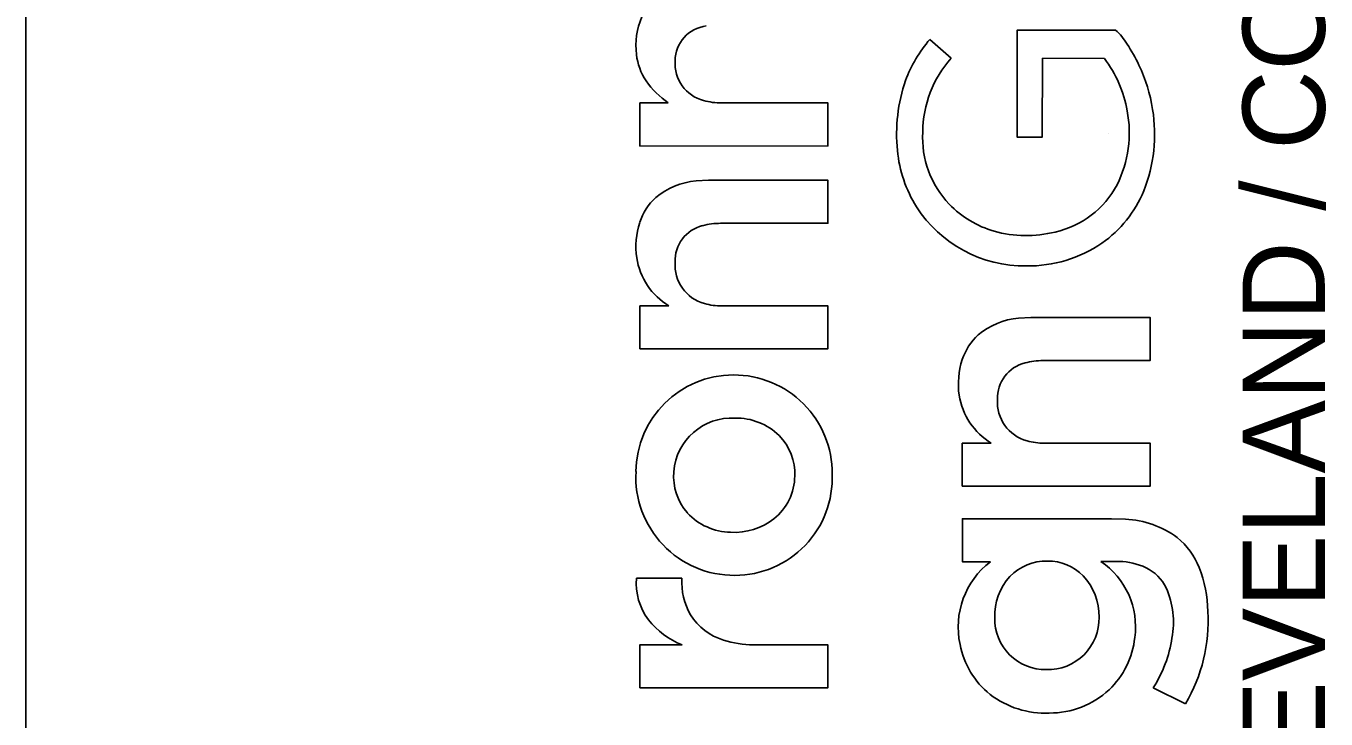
# Model space of a CAD drawing. Extents: x 0 to 1700, y 0 to 1100.
# Drawn here: x 1600 to 1645.05, y 154.72 to 178.74 of the extents above; entities that cross this region are included whole.
import ezdxf

# ---------------------------------------------------------------- set-up
doc = ezdxf.new("R2010")
doc.units = 0
doc.layers.add('SH_Border', color=7, linetype='Continuous')
doc.layers.add('SH_Data', color=7, linetype='Continuous')

msp = doc.modelspace()

# ---------------------------------------------------------------- linework, layer by layer
at = {"layer": 'SH_Border'}
msp.add_line((1600, 25), (1600, 1075), dxfattribs=at)
at = {"layer": 'SH_Data'}
for p, q in [((1634.34, 178.592), (1637.758, 178.596)), ((1634.34, 174.889), (1634.34, 178.592)), ((1631.318, 178.274), (1632.057, 177.621)), ((1635.224, 177.62), (1635.216, 174.888)), ((1637.368, 177.614), (1635.224, 177.62)), ((1621.271, 174.576), (1621.272, 176.069)), ((1621.272, 176.069), (1622.257, 176.069)), ((1624.103, 176.069), (1627.786, 176.068)), ((1627.786, 176.068), (1627.786, 174.578)), ((1635.216, 174.888), (1634.34, 174.889)), ((1637.5, 175), (1637.5, 175)), ((1627.786, 174.578), (1621.271, 174.576)), ((1623.219, 173.368), (1623.645, 173.391)), ((1623.645, 173.391), (1627.785, 173.391)), ((1627.785, 173.391), (1627.786, 171.902)), ((1627.786, 171.902), (1624.07, 171.898)), ((1621.271, 169.033), (1622.276, 169.036)), ((1621.271, 167.543), (1621.271, 169.033)), ((1624.111, 169.036), (1627.785, 169.036)), ((1627.785, 169.036), (1627.786, 167.548)), ((1634.392, 168.61), (1634.817, 168.633)), ((1634.817, 168.633), (1638.958, 168.633)), ((1638.958, 168.633), (1638.958, 167.144)), ((1627.786, 167.548), (1621.271, 167.543)), ((1638.958, 167.144), (1635.242, 167.14)), ((1632.444, 164.275), (1633.449, 164.277)), ((1632.444, 162.785), (1632.444, 164.275)), ((1635.284, 164.277), (1638.957, 164.277)), ((1638.957, 164.277), (1638.958, 162.789)), ((1638.958, 162.789), (1632.444, 162.785)), ((1632.445, 160.168), (1632.445, 161.661)), ((1632.445, 161.661), (1637.618, 161.661)), ((1637.618, 161.661), (1638.096, 161.643)), ((1633.418, 160.168), (1632.445, 160.168)), ((1637.881, 160.178), (1637.243, 160.181)), ((1621.149, 159.597), (1622.727, 159.597)), ((1621.271, 155.797), (1621.271, 157.289)), ((1621.271, 157.289), (1622.736, 157.289)), ((1625.206, 157.29), (1627.786, 157.287)), ((1627.786, 157.287), (1627.782, 155.797)), ((1627.782, 155.797), (1621.271, 155.797)), ((1640.18, 155.245), (1639.06, 155.799))]:
    msp.add_line(p, q, dxfattribs=at)
for points in [[(1637.368, 177.614), (1635.224, 177.62), (1635.216, 174.888), (1634.34, 174.889), (1634.34, 178.592), (1637.758, 178.596)], [(1631.318, 178.274), (1632.057, 177.621)], [(1621.271, 174.576), (1621.272, 176.069), (1622.257, 176.069)], [(1624.103, 176.069), (1627.786, 176.068), (1627.786, 174.578), (1621.271, 174.576)], [(1623.219, 173.368), (1623.645, 173.391), (1627.785, 173.391), (1627.786, 171.902), (1624.07, 171.898)], [(1621.271, 167.543), (1621.271, 169.033), (1622.276, 169.036)], [(1624.111, 169.036), (1627.785, 169.036), (1627.786, 167.548), (1621.271, 167.543)], [(1634.392, 168.61), (1634.817, 168.633), (1638.958, 168.633), (1638.958, 167.144), (1635.242, 167.14)], [(1632.444, 162.785), (1632.444, 164.275), (1633.449, 164.277)], [(1635.284, 164.277), (1638.957, 164.277), (1638.958, 162.789), (1632.444, 162.785)], [(1633.418, 160.168), (1632.445, 160.168), (1632.445, 161.661), (1637.618, 161.661), (1638.096, 161.643)], [(1637.881, 160.178), (1637.243, 160.181)], [(1621.149, 159.597), (1622.727, 159.597)], [(1625.206, 157.29), (1627.786, 157.287), (1627.782, 155.797), (1621.271, 155.797)], [(1621.271, 155.797), (1621.271, 157.289), (1622.736, 157.289)], [(1640.18, 155.245), (1639.06, 155.799)]]:
    msp.add_lwpolyline(points, dxfattribs=at)
for centre, radius, start, end in [((1623.572, 178.06), 2.439, 156.0638, 187.3493), ((1623.572, 178.06), 2.439, 156.0638, 187.3493), ((1623.711, 177.528), 1.217, 96.5532, 179.949), ((1623.711, 177.528), 1.217, 96.5532, 179.949), ((1636.249, 176.969), 2.219, 30.9891, 47.161), ((1636.249, 176.969), 2.219, 30.9891, 47.161), ((1635.081, 175.093), 4.928, 139.7948, 159.137), ((1635.081, 175.093), 4.928, 139.7948, 159.137), ((1633.546, 175.009), 5.553, 25.3031, 33.9618), ((1633.546, 175.009), 5.553, 25.3031, 33.9618), ((1623.23, 177.987), 2.091, 186.5579, 213.3885), ((1623.23, 177.987), 2.091, 186.5579, 213.3885), ((1623.804, 177.431), 1.314, 175.722, 255.7863), ((1623.804, 177.431), 1.314, 175.722, 255.7863), ((1634.95, 175.04), 3.877, 138.258, 179.7006), ((1634.95, 175.04), 3.877, 138.258, 179.7006), ((1633.944, 175.049), 4.278, 10.0751, 36.8319), ((1633.944, 175.049), 4.278, 10.0751, 36.8319), ((1633.52, 174.993), 5.583, 8.8034, 25.3348), ((1633.52, 174.993), 5.583, 8.8034, 25.3348), ((1623.943, 178.539), 2.99, 214.7043, 235.6872), ((1623.943, 178.539), 2.99, 214.7043, 235.6872), ((1635.935, 174.984), 5.768, 161.1438, 185.6281), ((1635.935, 174.984), 5.768, 161.1438, 185.6281), ((1624.097, 178.259), 2.19, 253.6672, 270.1498), ((1624.097, 178.259), 2.19, 253.6672, 270.1498), ((1634.212, 175.028), 4.018, 333.4669, 11.0367), ((1634.212, 175.028), 4.018, 333.4669, 11.0367), ((1633.782, 174.989), 5.325, 338.2887, 9.2855), ((1633.782, 174.989), 5.325, 338.2887, 9.2855), ((1634.406, 174.866), 3.338, 176.6658, 223.6912), ((1634.406, 174.866), 3.338, 176.6658, 223.6912), ((1634.668, 174.85), 4.493, 185.5077, 212.0129), ((1634.668, 174.85), 4.493, 185.5077, 212.0129), ((1623.435, 170.884), 2.494, 94.9706, 130.2248), ((1623.435, 170.884), 2.494, 94.9706, 130.2248), ((1634.934, 174.773), 3.26, 282.8815, 331.8147), ((1634.934, 174.773), 3.26, 282.8815, 331.8147), ((1634.918, 174.584), 4.12, 305.0306, 337.6757), ((1634.918, 174.584), 4.12, 305.0306, 337.6757), ((1623.174, 171.301), 2.008, 132.2238, 161.6823), ((1623.174, 171.301), 2.008, 132.2238, 161.6823), ((1634.523, 175.006), 3.519, 224.0215, 253.88), ((1634.523, 175.006), 3.519, 224.0215, 253.88), ((1634.606, 174.874), 4.454, 212.7022, 270.714), ((1634.606, 174.874), 4.454, 212.7022, 270.714), ((1623.936, 171.079), 2.801, 162.274, 187.7917), ((1623.936, 171.079), 2.801, 162.274, 187.7917), ((1623.741, 170.603), 1.249, 103.6868, 182.214), ((1623.741, 170.603), 1.249, 103.6868, 182.214), ((1624.054, 169.598), 2.3, 89.6051, 105.3303), ((1624.054, 169.598), 2.3, 89.6051, 105.3303), ((1634.659, 175.627), 4.154, 254.4535, 283.9512), ((1634.659, 175.627), 4.154, 254.4535, 283.9512), ((1634.715, 174.989), 4.569, 269.3273, 304.1963), ((1634.715, 174.989), 4.569, 269.3273, 304.1963), ((1623.513, 171.071), 2.381, 188.9646, 238.6987), ((1623.513, 171.071), 2.381, 188.9646, 238.6987), ((1623.868, 170.449), 1.378, 175.5844, 255.1382), ((1623.868, 170.449), 1.378, 175.5844, 255.1382), ((1624.092, 171.143), 2.107, 254.0891, 270.5284), ((1624.092, 171.143), 2.107, 254.0891, 270.5284), ((1634.608, 166.125), 2.494, 94.9706, 130.2248), ((1634.608, 166.125), 2.494, 94.9706, 130.2248), ((1634.347, 166.543), 2.008, 132.2238, 161.6823), ((1634.347, 166.543), 2.008, 132.2238, 161.6823), ((1635.109, 166.321), 2.801, 162.274, 187.7917), ((1635.109, 166.321), 2.801, 162.274, 187.7917), ((1635.227, 164.84), 2.3, 89.6051, 105.3303), ((1635.227, 164.84), 2.3, 89.6051, 105.3303), ((1634.914, 165.845), 1.249, 103.6868, 182.214), ((1634.914, 165.845), 1.249, 103.6868, 182.214), ((1624.507, 163.271), 3.37, 89.8476, 179.6405), ((1624.507, 163.271), 3.37, 89.8476, 179.6405), ((1624.529, 163.237), 3.405, 359.5401, 90.2114), ((1624.529, 163.237), 3.405, 359.5401, 90.2114), ((1634.686, 166.312), 2.381, 188.9646, 238.6987), ((1634.686, 166.312), 2.381, 188.9646, 238.6987), ((1635.04, 165.69), 1.378, 175.5844, 255.1382), ((1635.04, 165.69), 1.378, 175.5844, 255.1382), ((1624.461, 163.132), 2.02, 87.0481, 175.5726), ((1624.461, 163.132), 2.02, 87.0481, 175.5726), ((1624.602, 163), 2.149, 45.8426, 90.9801), ((1624.602, 163), 2.149, 45.8426, 90.9801), ((1624.729, 163.211), 1.911, 357.8857, 44.159), ((1624.729, 163.211), 1.911, 357.8857, 44.159), ((1635.264, 166.385), 2.107, 254.0891, 270.5284), ((1635.264, 166.385), 2.107, 254.0891, 270.5284), ((1624.541, 163.104), 3.409, 176.8344, 270.4038), ((1624.541, 163.104), 3.409, 176.8344, 270.4038), ((1624.365, 163.125), 1.924, 175.1538, 221.1471), ((1624.365, 163.125), 1.924, 175.1538, 221.1471), ((1624.562, 163.069), 3.374, 270.0624, 2.3776), ((1624.562, 163.069), 3.374, 270.0624, 2.3776), ((1624.723, 163.159), 1.915, 308.2894, 359.4347), ((1624.723, 163.159), 1.915, 308.2894, 359.4347), ((1624.459, 163.303), 2.114, 223.0999, 268.8089), ((1624.459, 163.303), 2.114, 223.0999, 268.8089), ((1624.548, 163.395), 2.209, 266.5651, 308.0608), ((1624.548, 163.395), 2.209, 266.5651, 308.0608), ((1637.953, 158.394), 3.251, 53.4034, 87.4906), ((1637.953, 158.394), 3.251, 53.4034, 87.4906), ((1638.259, 159.02), 2.571, 21.6075, 50.5577), ((1638.259, 159.02), 2.571, 21.6075, 50.5577), ((1635.146, 157.906), 2.846, 127.3748, 192.2247), ((1635.146, 157.906), 2.846, 127.3748, 192.2247), ((1635.347, 158.464), 1.73, 88.473, 136.4256), ((1635.347, 158.464), 1.73, 88.473, 136.4256), ((1635.407, 158.481), 1.712, 44.2719, 90.4762), ((1635.407, 158.481), 1.712, 44.2719, 90.4762), ((1635.71, 157.914), 2.736, 352.1125, 55.923), ((1635.71, 157.914), 2.736, 352.1125, 55.923), ((1637.833, 157.862), 2.316, 65.0169, 88.8011), ((1637.833, 157.862), 2.316, 65.0169, 88.8011), ((1638.13, 158.578), 1.543, 26.2681, 63.803), ((1638.13, 158.578), 1.543, 26.2681, 63.803), ((1636.535, 158.357), 4.418, 1.1514, 21.3627), ((1636.535, 158.357), 4.418, 1.1514, 21.3627), ((1623.308, 159.441), 2.164, 175.8731, 216.3475), ((1623.308, 159.441), 2.164, 175.8731, 216.3475), ((1625.043, 159.474), 2.32, 176.9688, 209.6064), ((1625.043, 159.474), 2.32, 176.9688, 209.6064), ((1635.571, 158.301), 2.005, 137.4674, 182.3324), ((1635.571, 158.301), 2.005, 137.4674, 182.3324), ((1635.184, 158.3), 1.998, 358.5714, 43.5376), ((1635.184, 158.3), 1.998, 358.5714, 43.5376), ((1636.783, 158.077), 2.976, 349.3073, 23.4307), ((1636.783, 158.077), 2.976, 349.3073, 23.4307), ((1623.733, 159.858), 2.755, 218.0981, 248.7907), ((1623.733, 159.858), 2.755, 218.0981, 248.7907), ((1624.757, 159.407), 2.039, 211.9447, 253.2028), ((1624.757, 159.407), 2.039, 211.9447, 253.2028), ((1635.323, 158.185), 1.755, 178.8821, 271.0837), ((1635.323, 158.185), 1.755, 178.8821, 271.0837), ((1635.409, 158.202), 1.773, 268.2788, 1.5502), ((1635.409, 158.202), 1.773, 268.2788, 1.5502), ((1635.269, 158.122), 5.692, 329.6388, 3.26), ((1635.269, 158.122), 5.692, 329.6388, 3.26), ((1625.233, 160.825), 3.535, 252.4655, 269.573), ((1625.233, 160.825), 3.535, 252.4655, 269.573), ((1635.232, 157.848), 2.919, 190.7518, 231.2892), ((1635.232, 157.848), 2.919, 190.7518, 231.2892), ((1635.494, 157.854), 2.944, 313.742, 353.8554), ((1635.494, 157.854), 2.944, 313.742, 353.8554), ((1635.369, 158.167), 4.385, 327.3149, 351.5748), ((1635.369, 158.167), 4.385, 327.3149, 351.5748), ((1635.316, 158.056), 3.134, 232.4606, 272.5902), ((1635.316, 158.056), 3.134, 232.4606, 272.5902), ((1635.477, 157.951), 3.026, 269.6361, 312.7088), ((1635.477, 157.951), 3.026, 269.6361, 312.7088)]:
    msp.add_arc(centre, radius, start, end, dxfattribs=at)

# ---------------------------------------------------------------- texts
msp.add_text('AKRON / CLEVELAND / COLUMBUS', height=2.84845, rotation=90, dxfattribs=at).set_placement((1645.006, 131.9))

doc.saveas('drawing.dxf')
